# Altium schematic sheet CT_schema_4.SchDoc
size 371 x 245 mm
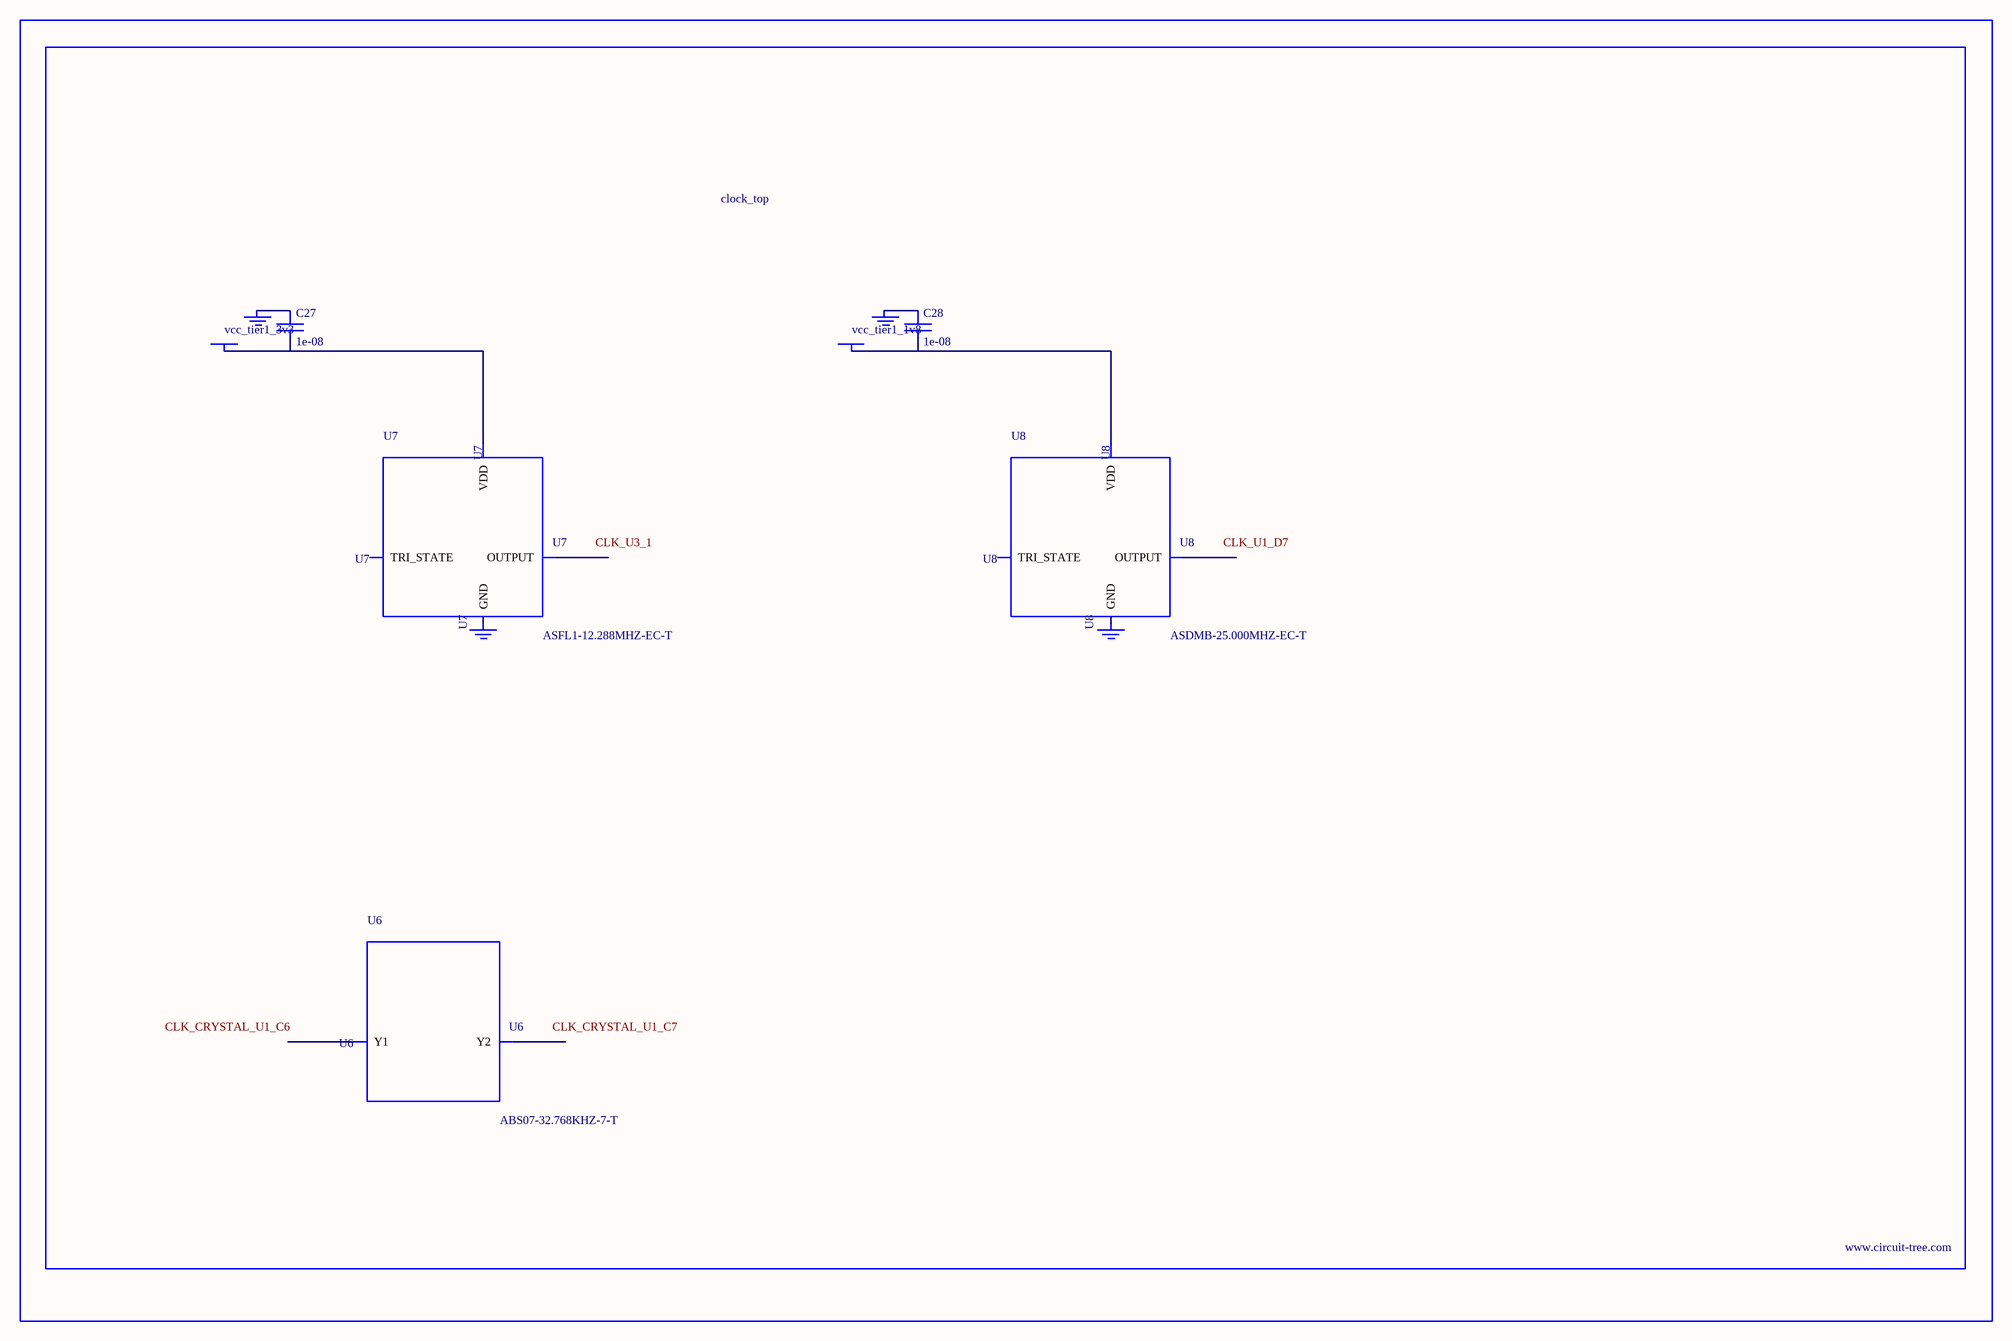
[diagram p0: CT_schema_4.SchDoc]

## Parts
BORDER3  (no value)
C27  1e-08  [C0402]
C28  1e-08  [C0402]
GND_INSTANCE_3_0  (no value)
GND_INSTANCE_3_1  (no value)
GND_INSTANCE_3_2  (no value)
GND_INSTANCE_3_3  (no value)
POWER_INSTANCE_3_0  vcc_tier1_3v3
POWER_INSTANCE_3_1  vcc_tier1_1v8
U6  ABS07-32.768KHZ-7-T  [ABS07-32.768KHZ-7-T]
U7  ASFL1-12.288MHZ-EC-T  [ASFL1]
U8  ASDMB-25.000MHZ-EC-T  [ASDMB-XX.XXXXMHZ-XX-XX-XXX]

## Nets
NetC27_1: C27.1 GND_INSTANCE_3_0.0(GND)
NetC27_2: C27.2 POWER_INSTANCE_3_0.0(PWR) U7.4(VDD)
NetC28_1: C28.1 GND_INSTANCE_3_2.0(GND)
NetC28_2: C28.2 POWER_INSTANCE_3_1.0(PWR) U8.4(VDD)

Not connected (* = marked no-connect by the designer): GND_INSTANCE_3_1 0(GND); GND_INSTANCE_3_3 0(GND); U6 1(Y1) 2(Y2); U7 1(TRI_STATE) 2(GND) 3(OUTPUT); U8 1(TRI_STATE) 2(GND) 3(OUTPUT)

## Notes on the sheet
- Labels drawn without touching a wire or pin: CLK_CRYSTAL_U1_C6, CLK_CRYSTAL_U1_C7, CLK_U1_D7, CLK_U3_1

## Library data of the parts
BORDER3 = BORDER_PAGE3
C27 C28 = C0402C103K3RAC
GND_INSTANCE_3_0-GND_INSTANCE_3_3 = GND
POWER_INSTANCE_3_0 POWER_INSTANCE_3_1 = PWR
